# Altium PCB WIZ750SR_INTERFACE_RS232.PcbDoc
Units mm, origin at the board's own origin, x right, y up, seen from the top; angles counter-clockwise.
Board outline 83 x 65 mm, 2 copper layers (Top Layer, Bottom Layer), stack 0.325 mm thick; 76 components, 69 nets, 279 pads, 112 vias.
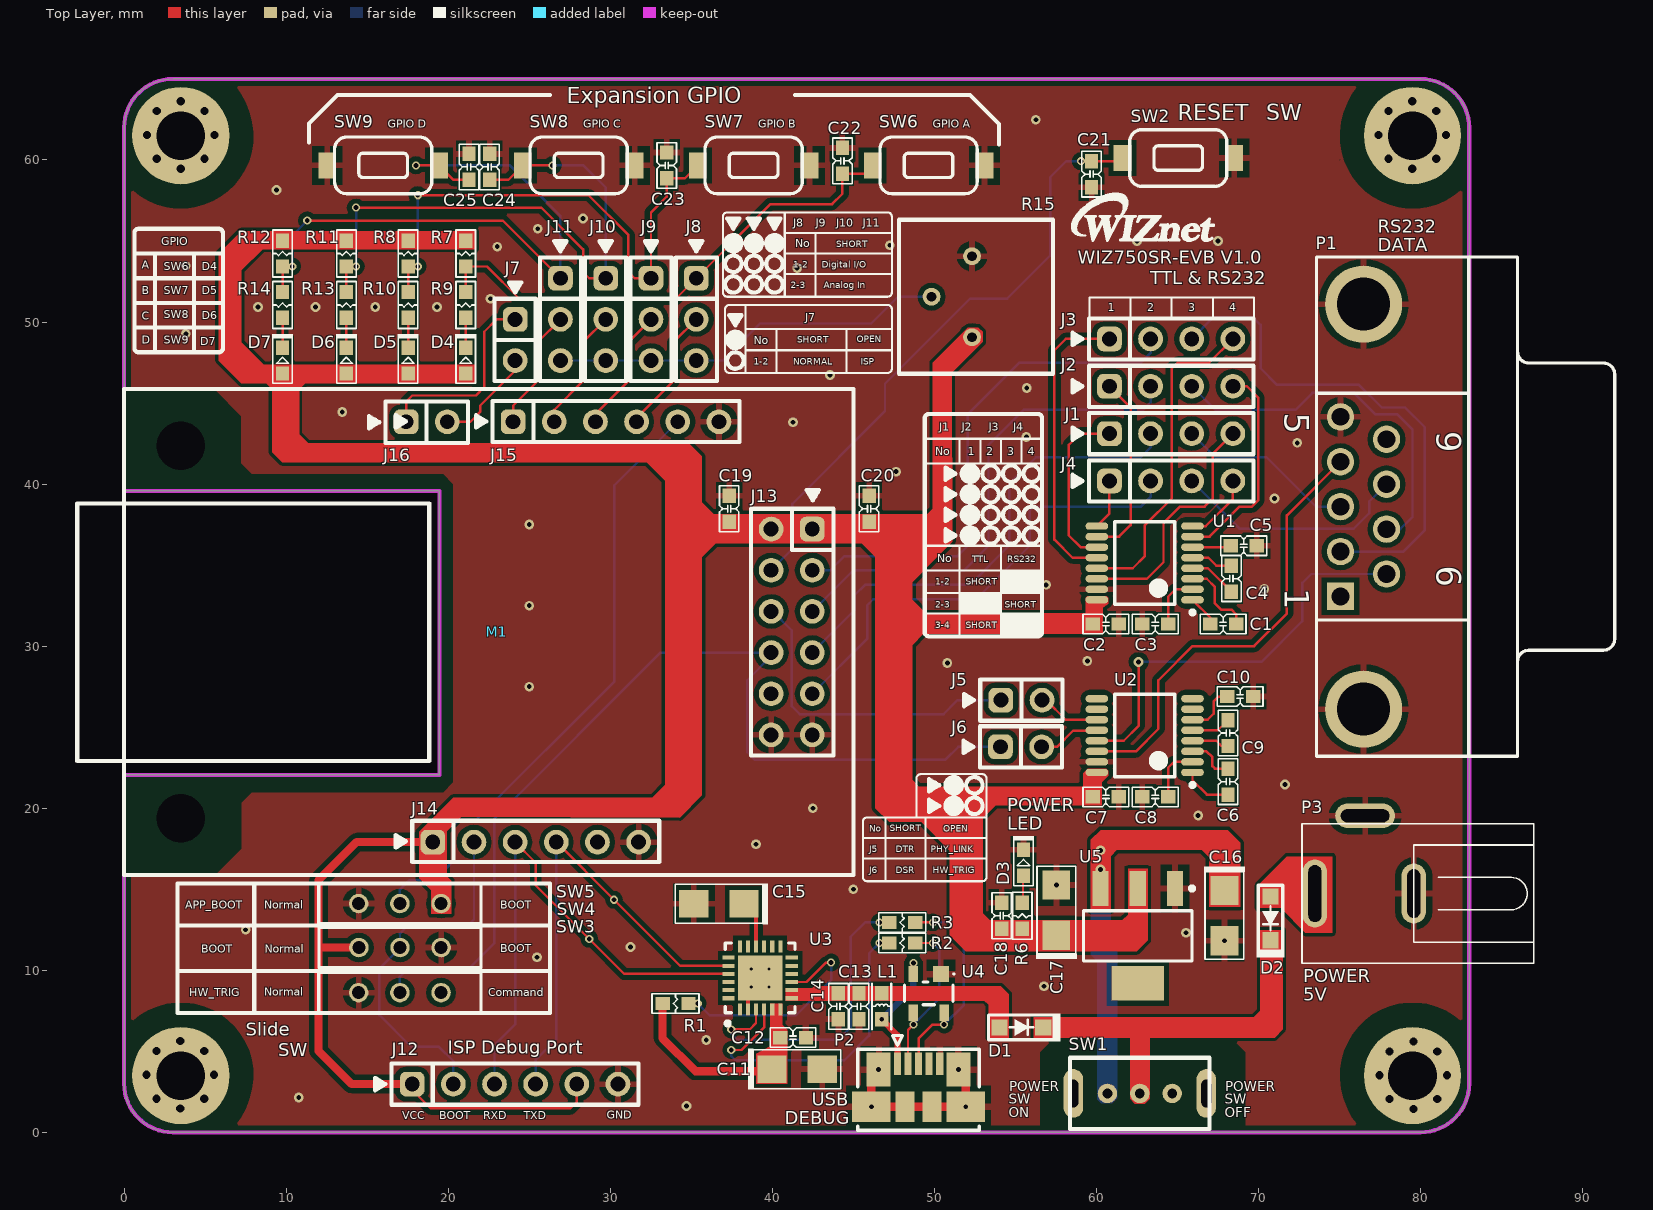
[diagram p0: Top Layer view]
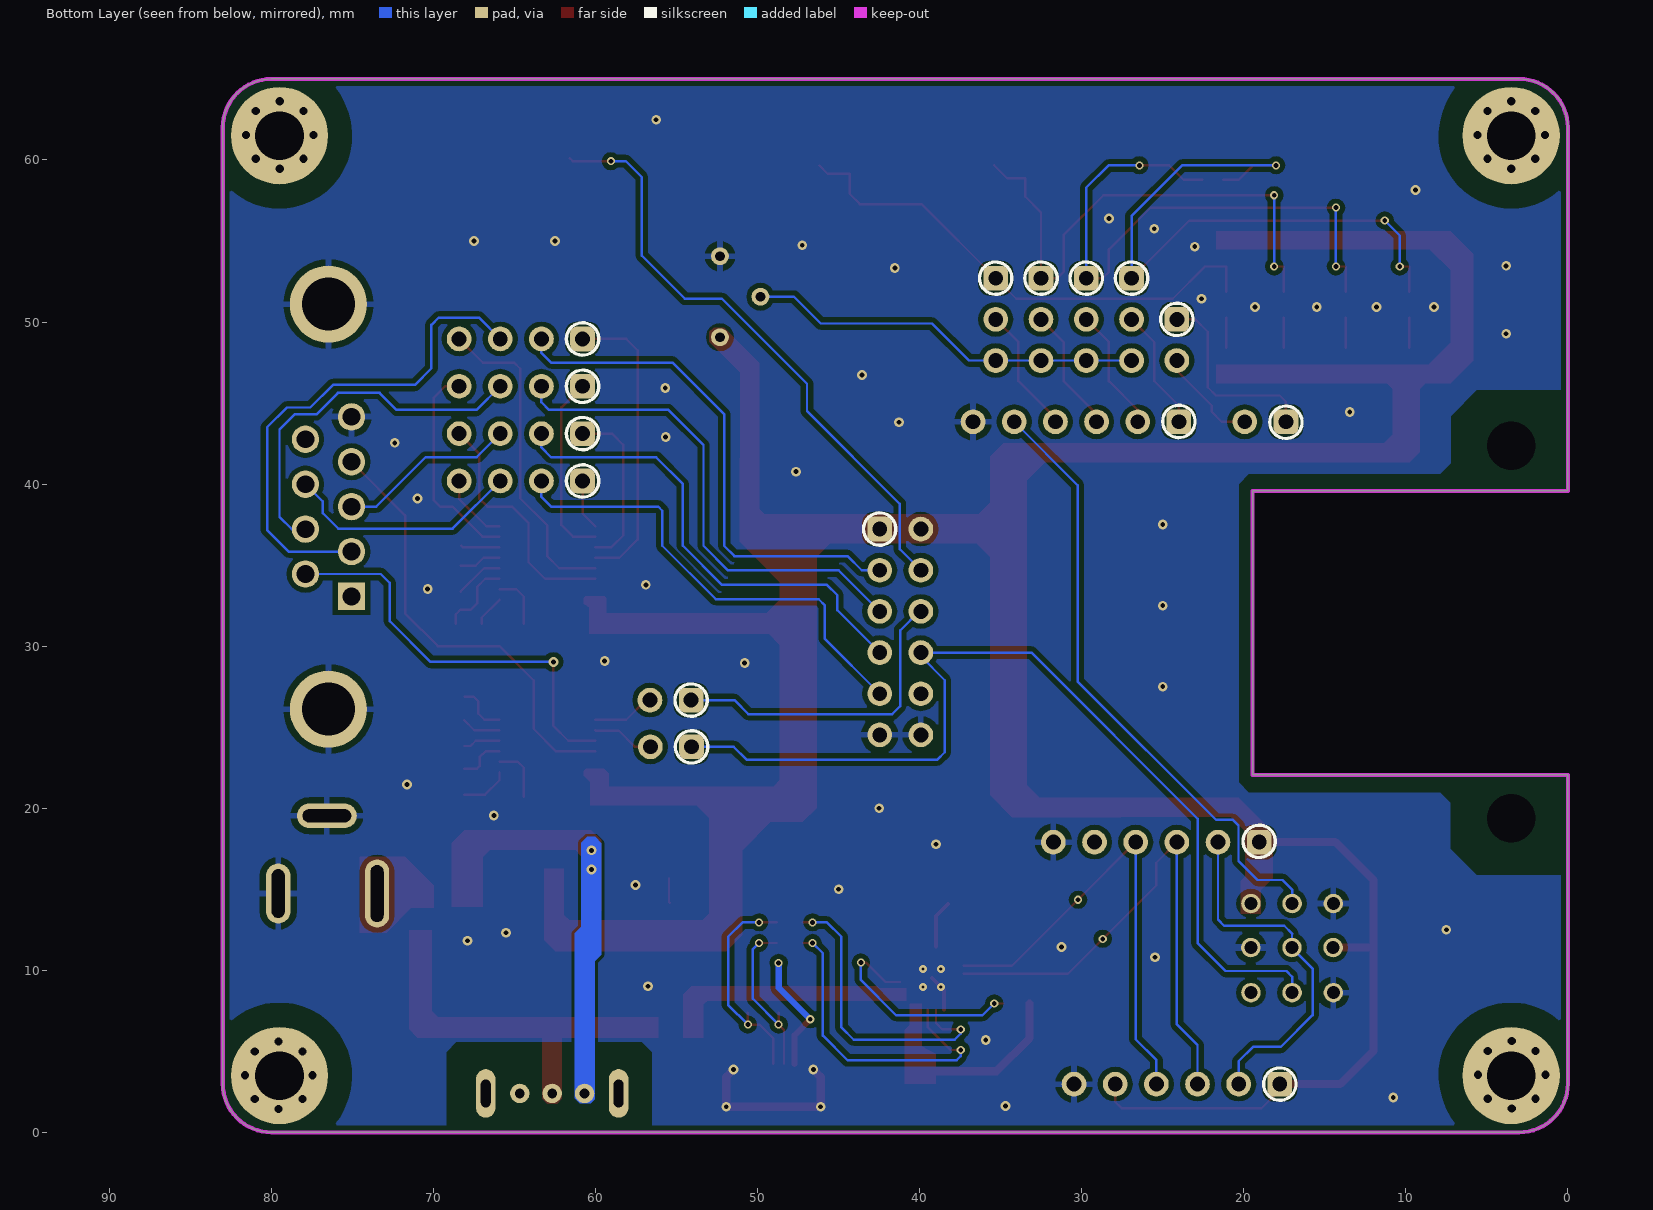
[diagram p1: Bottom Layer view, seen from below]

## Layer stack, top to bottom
Top Solder: solder mask 0.0102, Solder Resist, Dk 3.5
Top Layer: signal copper 0.0356
Dielectric 1: core 0.254, FR-4, Dk 4.2
Bottom Layer: signal copper 0.0356
Bottom Solder: solder mask 0.0102, Solder Resist, Dk 3.5

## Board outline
0,3 ccw(c3,3) 3,0 80,0 ccw(c80,3) 83,3 83,62 ccw(c80,62) 80,65 3,65 ccw(c3,62) 0,62 0,39.575 19.45,39.575 19.45,22.05 0,22.05

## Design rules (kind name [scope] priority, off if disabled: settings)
Clearance [All] p1: gap=0.15 except(0.205: Track-Region SMDPad-Region THPad-Region Via-Region Fill-Region Poly-Region Region-Region; 0.3: Track-Poly SMDPad-Poly THPad-Poly Via-Poly Fill-Poly Poly-Poly; 0.381: Arc-Poly)
HoleSize [All] p1: absolutevalues=TRUE maxlimit=4.064 minlimit=0.025 maxpercent=80.000 minpercent=20.000
MinimumSolderMaskSliver [All] p1: minsoldermaskwidth=0.1
PlaneClearance [All] p1: clearance=0.3
PlaneConnect [All] p1: planeconnectstyle=Direct reliefexpansion=0.508 reliefentries=4 reliefconductorwidth=0.254 reliefairgap=0.254
PolygonConnect PolygonConnect_2 [IsPad vs IsNamedPolygon('TOPGND') Or IsNamedPolygon('BOTGND')] p1: connectstyle=Relief reliefconductorwidth=0.381 reliefentries=4 polygonreliefangle="90 Angle" airgapwidth=0.381
PolygonConnect PolygonConnect_1 [IsVia] p2: connectstyle=Direct reliefconductorwidth=0.254 reliefentries=4 polygonreliefangle="90 Angle" airgapwidth=0.254
PolygonConnect [All] p3: connectstyle=Direct reliefconductorwidth=0.381 reliefentries=4 polygonreliefangle="90 Angle" airgapwidth=0.381
RoutingVias [All] p1: holewidth=0.3 width=0.5 viastyle="Through Hole" minholewidth=0.2 minwidth=0.5 maxholewidth=1 maxwidth=1.5
SilkToSilkClearance [All] p1: silktosilkclearance=0.1
SilkToSolderMaskClearance [IsPad] p1: minsilkscreentomaskgap=0 clearancetoexposedcopper=TRUE
SolderMaskExpansion [All] p1: expansion=0.1
Width [All] p1: maxlimit=0.508 minlimit=0.15 preferedwidth=0.15
24 further rules are at their usual default settings.

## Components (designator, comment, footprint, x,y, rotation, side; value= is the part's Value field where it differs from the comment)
C1 "0.1uF" CAP-0603 67.818,31.369 r180 top
C2 "0.1uF" CAP-0603 60.579,31.369 r0 top
C3 "0.1uF" CAP-0603 63.627,31.369 r180 top
C4 "0.1uF" CAP-0603 68.326,34.163 r270 top
C5 "0.1uF" CAP-0603 69.088,36.195 r0 top
C6 "0.1uF" CAP-0603 68.115,21.64 r270 top
C7 "0.1uF" CAP-0603 60.579,20.701 r0 top
C8 "0.1uF" CAP-0603 63.627,20.701 r180 top
C9 "0.1uF" CAP-0603 68.115,24.64 r270 top
C10 "0.1uF" CAP-0603 68.865,26.89 r0 top
C11 "4.7uF/16V" "CAP-A Size" 41.525,3.9 r0 top
C12 "0.1uF" CAP-0603 41.275,5.842 r180 top
C13 "1uF" CAP-0603 45.35,7.775 r90 top
C14 "0.1uF" CAP-0603 44.075,7.775 r90 top
C15 "4.7uF/16V" "CAP-A Size" 36.703,14.097 r180 top
C16 "10uF/16V" "CAP-A Size" 67.9,13.375 r270 top
C17 "10uF/16V" "CAP-A Size" 57.531,13.716 r90 top
C18 "0.1uF" CAP-0603 54.152,13.363 r270 top
C19 "0.1uF" CAP-0603 37.338,38.481 r270 top
C20 "0.1uF" CAP-0603 45.974,38.481 r270 top
C21 "0.1uF" CAP-0603 59.7,59.125 r90 top
C22 "0.1uF" CAP-0603 44.323,59.944 r270 top
C23 "0.1uF" CAP-0603 33.483,59.661 r270 top
C24 "0.1uF" CAP-0603 22.556,59.572 r270 top
C25 "0.1uF" CAP-0603 21.281,59.572 r270 top
D1 "BAT60A" D-BAT60A/SOD-323 55.372,6.477 r0 top (schematic designator D3)
D2 "BAT60A" D-BAT60A/SOD-323 70.739,13.208 r270 top (schematic designator D4)
D3 "GREEN-0603" LED-0603-RED 55.499,16.637 r90 top (schematic designator D5)
D4 "GREEN-0603" LED-0603-GREEN 21.082,47.625 r90 top (schematic designator D6)
D5 "GREEN-0603" LED-0603-GREEN 17.526,47.625 r90 top (schematic designator D7)
D6 "GREEN-0603" LED-0603-GREEN 13.716,47.625 r90 top (schematic designator D8)
D7 "GREEN-0603" LED-0603-GREEN 9.779,47.625 r90 top (schematic designator D9)
J1 "2.54mm 1x4 Pin Header DIP" IDC-1X4 60.799,43.115 r0 top
J2 "2.54mm 1x4 Pin Header DIP" IDC-1X4 60.799,46.036 r0 top
J3 "2.54mm 1x4 Pin Header DIP" IDC-1X4 60.799,48.957 r0 top
J4 "2.54mm 1x4 Pin Header DIP" IDC-1X4 60.799,40.194 r0 top
J5 "2.54mm 1x2 Pin Header DIP" IDC-1X2 54.102,26.67 r0 top
J6 "2.54mm 1x2 Pin Header DIP" IDC-1X2 54.075,23.787 r0 top
J7 "2.54mm 1x2 Pin Header DIP" IDC-1X2 24.13,50.165 r270 top
J8 "2.54mm 1x3 Pin Header DIP" IDC-1X3 35.306,52.705 r270 top
J9 "2.54mm 1x3 Pin Header DIP" IDC-1X3 32.512,52.705 r270 top
J10 "2.54mm 1x3 Pin Header DIP" IDC-1X3 29.718,52.705 r270 top
J11 "2.54mm 1x3 Pin Header DIP" IDC-1X3 26.924,52.705 r270 top
J12 "2.54mm 1x6 Pin Header DIP" IDC-1X6 17.775,2.975 r0 top
L1 "HH-1M1608-121JT" IND-0603 46.75,7.775 r90 top
M1 "WIZ750SR_TTL/232" WIZ750SR_V1.0_TTL/232 0,15.875 r0 top
P1 "D-SUB9-MALE" D-SUB9-MALE 85.979,38.608 r270 top
P2 "47346-0001" USB-MICRO-B(SMD) 49.022,0.127 r90 top
P3 "DC-JACK 2pi" "DC-JACK 2pi" 76.581,14.732 r90 top
R1 "4.7K" RES-0603 34.025,7.95 r180 top
R2 "22R" RES-0603 48.006,11.684 r180 top
R3 "22R" RES-0603 48.006,12.954 r180 top
R6 "330R" RES-0603 55.422,13.363 r90 top
R7 "4.7K" RES-0603 21.082,54.229 r90 top
R8 "4.7K" RES-0603 17.526,54.229 r90 top
R9 "330R" RES-0603 21.082,51.054 r90 top
R10 "330R" RES-0603 17.526,51.054 r90 top
R11 "4.7K" RES-0603 13.716,54.229 r90 top
R12 "4.7K" RES-0603 9.779,54.229 r90 top
R13 "330R" RES-0603 13.716,51.054 r90 top
R14 "330R" RES-0603 9.779,51.054 r90 top
R15 "WIW3386P" WIW3386P 52.324,51.562 r270 top
SW1 "SK-12D02" SK-12D02 62.675,2.4 r0 top
SW2 "IT-1101NHA-180G" IT-1101NHA 65.047,60.12 r0 top
SW3 "ITS-12H" ITS-12H 17.016,8.616 r180 top
SW4 "ITS-12H" ITS-12H 17.025,11.4 r0 top
SW5 "ITS-12H" ITS-12H 17.016,14.116 r180 top
SW6 "IT-1101NHA-180G" IT-1101NHA 49.641,59.666 r180 top
SW7 "IT-1101NHA-180G" IT-1101NHA 38.846,59.666 r180 top
SW8 "IT-1101NHA-180G" IT-1101NHA 28.051,59.666 r180 top
SW9 "IT-1101NHA-180G" IT-1101NHA 15.986,59.666 r0 top
U1 "SP3232EBEY" SP3232EBEY-TSSOP16 62.976,35.133 r180 top
U2 "SP3232EBEY" SP3232EBEY-TSSOP16 62.976,24.485 r180 top
U3 "CP2104-GM" CP2104_QFN24_PAD 39.243,9.525 r90 top
U4 "SP0503BAHTG" SP0503BAHTG 49.65,8.575 r270 top
U5 "IL1117C-33ET" IL1117C-33ET 62.55,12.125 r270 top

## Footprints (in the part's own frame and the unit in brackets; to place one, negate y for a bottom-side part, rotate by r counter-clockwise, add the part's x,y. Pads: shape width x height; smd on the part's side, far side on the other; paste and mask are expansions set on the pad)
CAP-0603 [mm] "Ceramic CAP 0603(1608)"
  rect 0.89x0.82 smd: 1(-0.8,0) 2(0.8,0)
  silkscreen extent -1.41,-0.6 1.41,0.6, body extent -0.93,-0.41 0.93,0.41, height 0.81
"CAP-A Size" [mm] "Tantal CAP A Size EIA/IECQ 3216"
  rect 1.8x1.7 smd: 1(-1.55,0) 2(1.55,0)
  silkscreen extent -3,-1.25 2.7,1.25, body extent -1.67,-0.78 1.72,0.82, height 1.75
CP2104_QFN24_PAD [mm] "QFN, 24-Leads, Body 4.00x4.00mm, Pitch 0.50mm, Thermal Pad 2.75x2.75mm, IPC Medium Density"
  rect 0.75x0.25 smd: 1(-1.95,1.25) 2(-1.95,0.75) 3(-1.95,0.25) 4(-1.95,-0.25) 5(-1.95,-0.75) 6(-1.95,-1.25) 13(1.95,-1.25) 14(1.95,-0.75) 15(1.95,-0.25) 16(1.95,0.25) 17(1.95,0.75) 18(1.95,1.25)
  rect 0.25x0.75 smd: 7(-1.25,-1.95) 8(-0.75,-1.95) 9(-0.25,-1.95) 10(0.25,-1.95) 11(0.75,-1.95) 12(1.25,-1.95) 19(1.25,1.95) 20(0.75,1.95) 21(0.25,1.95) 22(-0.25,1.95) 23(-0.75,1.95) 24(-1.25,1.95)
  rect 2.75x2.75 smd: 25(0,0)
  silkscreen extent -2.92,-2.15 2.15,2.15, body extent -2,-2 2,2, height 0.8
D-BAT60A/SOD-323 [mm]
  rect 1x1 smd: 1(1.35,0) 2(-1.35,0)
  silkscreen extent -2.03,-0.86 2.41,0.86, body extent -1.35,-0.68 1.35,0.67, height 0.79
D-SUB9-MALE [mm] "D-SUB9, MALE, Right Angle;"
  rect 1.69x1.69 hole 1.09: 1(5.54,-10.92)
  round 1.69 hole 1.09: 2(2.77,-10.92) 3(0,-10.92) 4(-2.77,-10.92) 5(-5.54,-10.92) 6(4.155,-8.08) 7(1.385,-8.08) 8(-1.385,-8.08) 9(-4.155,-8.08)
  round 4.76 hole 3.26: 10(-12.495,-9.5) 11(12.495,-9.5)
  silkscreen extent -15.4,-12.4 15.4,6, body extent -15.38,-12.55 15.43,6.05, height 12.57
"DC-JACK 2pi" [mm] "DC-JACK 2pi"
  oval 4.2x1.5 hole 0.8 slot 3.5 at 0 deg: 1(0,3.1)
  oval 1.5x3.7 hole 0.8 slot 3 at 90 deg: 2(4.8,0)
  oval 3.7x1.5 hole 0.8 slot 3 at 0 deg: 3(0,-3)
  silkscreen extent -4.3,-10.4 4.3,3.9, body extent -4.42,-10.49 5.05,3.99, height 11.18
IDC-1X2 [mil]
  rrect50% 60x60 hole 36: 1(0,0)
  round 60 hole 36: 2(100,0)
  silkscreen extent -90,-50 150,50, body extent -49,-49 151,51, height 336
IDC-1X3 [mil]
  rrect50% 60x60 hole 36: 1(0,0)
  round 60 hole 36: 2(100,0) 3(200,0)
  silkscreen extent -90,-50 250,50, body extent -46,-49 254,49, height 323
IDC-1X4 [mil]
  rrect50% 60x60 hole 36: 1(0,0)
  round 60 hole 36: 2(100,0) 3(200,0) 4(300,0)
  silkscreen extent -90,-50 350,50, body extent -49,-49 351,51, height 336
IDC-1X6 [mil] "6-Way 2.54 mm Male Header"
  rrect50% 60x60 hole 36: 1(0,0)
  round 60 hole 36: 2(100,0) 3(200,0) 4(300,0) 5(400,0) 6(500,0)
  silkscreen extent -90,-50 550,50, body extent -49,-49 551,51, height 336
IL1117C-33ET [mm] "SOT223, 4-Leads, Body 6.45x7.80mm (avg), Pitch 2.30mm, IPC Medium Density"
  rect 2.15x1 smd: 1(-2.925,2.3) 2(-2.925,0) 3(-2.925,-2.3)
  rect 2.15x3.25 smd: 4(2.925,0)
  silkscreen extent -3.05,-3.35 1.55,3.48, body extent -3.54,-3.25 3.54,3.25, height 1.65
IND-0603 [mm]
  rect 0.89x0.82 smd: 1(-0.8,0) 2(0.8,0)
  silkscreen extent -1.4,-0.6 1.4,0.6, body extent -0.8,-0.4 0.8,0.4, height 0.95
IT-1101NHA [mm]
  rect 1.1x1.6 smd: 1(-3.45,0) 2(3.45,0)
  silkscreen extent -3,-1.75 3,1.75, body extent -3.05,-1.85 3.05,1.85, height 2.5
ITS-12H [mm] "Silde Switch"
  round 1.2 hole 0.8: 1(0,0) 2(-2.54,0) 3(2.54,0)
  silkscreen extent -5,-1.25 5,1.25, body extent -5,-1.22 5,1.22, height 6.4
LED-0603-GREEN [mm] "LED-0603-GREEN"
  rect 0.89x0.82 smd: 1(-0.8,0) 2(0.8,0)
  silkscreen extent -1.41,-0.65 1.65,0.65, body extent -0.85,-0.45 0.85,0.45, height 0.9
LED-0603-RED [mm] "LED-0603-RED"
  rect 0.89x0.82 smd: 1(-0.8,0) 2(0.8,0)
  silkscreen extent -1.41,-0.65 1.65,0.65, body extent -0.85,-0.45 0.85,0.45, height 0.9
RES-0603 [mm] "RES-0603"
  rect 0.89x0.82 smd: 1(-0.8,0) 2(0.8,0)
  silkscreen extent -1.45,-0.6 1.45,0.6, body extent -0.82,-0.41 0.82,0.41, height 0.46
SK-12D02 [mm] "Angle Type, DIP Switch, ON-ON, DC 50V, 0.3A"
  round 1.2 hole 0.6: 1(-2,0) 2(0,0) 3(2,0)
  oval 1.2x3 hole 0.6 slot 1.7 at 90 deg: 4(-4.1,0) 5(4.1,0)
  silkscreen extent -4.3,-2.2 4.3,2.2, body extent -4.31,-6.22 4.31,2.15, height 5
SP0503BAHTG [mm] "SOT143, 4-Leads, Body 2.92x2.37mm, Pitch 1.90mm, IPC Medium Density"
  rect 1x1 smd: 1(-1.2,0.75)
  rect 1x0.6 smd: 2(-1.2,-0.95) 3(1.2,-0.95) 4(1.2,0.95)
  silkscreen extent -1.25,-1.5 0.7,1.6, body extent -0.7,-1.52 0.7,1.52, height 1.22
SP3232EBEY-TSSOP16 [mm] "True +3.0V to +5.5V RS-232 Transceivers"
  oval 1.4x0.45 smd: 1(-2.95,2.275) 2(-2.95,1.625) 3(-2.95,0.975) 4(-2.95,0.325) 5(-2.95,-0.325) 6(-2.95,-0.975) 7(-2.95,-1.625) 8(-2.95,-2.275) 9(2.95,-2.275) 10(2.95,-1.625) 11(2.95,-0.975) 12(2.95,-0.325) 13(2.95,0.325) 14(2.95,0.975) 15(2.95,1.625) 16(2.95,2.275)
  silkscreen extent -3.08,-2.55 1.85,3.17, body extent -3.16,-2.49 3.12,2.51, height 1.09
USB-MICRO-B(SMD) [mm] "MOLEX SD-47346-001"
  rect 1.38x0.45 smd: 1(4.11,1.3) 2(4.11,0.65) 3(4.11,0) 4(4.11,-0.65) 5(4.11,-1.3)
  rect 2.1x1.475 smd: 6(3.75,2.462) 7(3.75,-2.462)
  rect 1.9x2.375 smd: 8(1.45,2.913) 11(1.45,-2.913)
  rect 1.9x1.175 smd: 9(1.45,0.837) 10(1.45,-0.837)
  silkscreen extent 0,-3.75 5.85,3.75, body extent -0.43,-4.1 5,4.1, height 2.98
WIW3386P [mm] "Potentiometer 10KR, Hongxing, 8mm shaft"
  round 1.1 hole 0.6: 1(2.5,0) 2(0,-2.5) 3(-2.5,0)
  silkscreen extent -4.75,-4.5 4.75,5, body extent -3.3,-3.3 3.3,3.75, height 4.7
WIZ750SR_V1.0_TTL/232 [mil] "WIZ750SR_V1.0, Serial to Ethernet Module, W7500P"
  round 0 hole 118.11: CH_GND(137.8,137.8) CH_GND(137.8,1043.31)
  rrect50% 60x60 hole 36: D1(1671.89,840.55) E1(945,1101.1) I1(750,80) W1(685,1101.1)
  round 60 hole 36: D2(1571.89,840.55) D3(1671.89,740.55) D4(1571.89,740.55) D5(1671.89,640.55) D6(1571.89,640.55) D7(1671.89,540.55) D8(1571.89,540.55) D9(1671.89,440.55) D10(1571.89,440.55) D11(1671.89,340.55) D12(1571.89,340.55) E2(1045,1101.1) E3(1145,1101.1) E4(1245,1101.1) E5(1345,1101.1) E6(1445,1101.1) I2(850,80) I3(950,80) I4(1050,80) I5(1150,80) I6(1250,80) W2(785,1101.1)
  silkscreen extent -114,0 1772,1181, body extent 625,29 1715,1149, height 325

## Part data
C1 C2 C3 C4 C5 C6 C7 C8 C9 C10 C12 C13 C14 C18 C19 C20 C21 C22 C23 C24 C25: library part CAP-0603, "Ceramic CAP 0603(1608)"
C11 C15 C16 C17: library part "CAP-A Size", "Tantla CAP A Size EIA/IECQ 3216"
D1 D2: library part DIODE-BAT60A, "Silicon Schottky Diode"
D3 D4 D5 D6 D7: library part LED-0603, "LED-0603"
J5 J6 J7: library part "Header 2", "Header, 2-Pin"
J12: library part "Header 6", "Header, 6-Pin"
L1: library part IND-0603, "Inductor 0603(1608)"
M1: library part WIZ750SR_V1.0_TTL/232, "Serial to ethernet module, 45mmx30mm, TTL/232"
P1: "D-SUB-9, MALE,  Right Angle"
P2: "MICRO USB B Type"
R1 R2 R3 R6 R7 R8 R9 R10 R11 R12 R13 R14: library part RES-0603, "RES-0603"
R15: "Potentiometer"
SW1: "3 Port SW , SPDT ON-ON , 50V, 0.3A"
SW2 SW6 SW7 SW8 SW9: "TACT Switch (SMD)"
SW3 SW4 SW5: "Slide Switch"
U1 U2: "True +3.0V to +5.5V RS-232 Transceivers"
U3: "USB to UART Bridge, SiliconLabs"
U4: "Little Fuse, Silicon Protection Array Products"
U5: "1A, 3.3V"

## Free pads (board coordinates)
  round 6 hole 3: ""(3.5,3.5) ""(3.5,61.5) ""(79.5,3.5) ""(79.5,61.5)

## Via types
v1: diameter 0.6, hole 0.3, Top Layer to Bottom Layer, tented both sides, 53 vias
v2: diameter 0.762, hole 0.508, Top Layer to Bottom Layer, tented both sides, 32 vias
v3: diameter 0.5, hole 0.3, Top Layer to Bottom Layer, tented both sides, 19 vias
v4: diameter 0.5, hole 0.2, Top Layer to Bottom Layer, 4 vias
v5: diameter 0.5, hole 0.3, Top Layer to Bottom Layer, 4 vias

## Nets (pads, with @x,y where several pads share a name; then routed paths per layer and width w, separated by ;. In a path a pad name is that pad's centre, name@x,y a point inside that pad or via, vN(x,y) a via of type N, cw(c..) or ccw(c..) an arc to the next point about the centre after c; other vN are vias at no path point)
5V: C16.1 SW1.1 U5.3
  other v1: 60.25,16.225 60.25,17.4
ADC0: J8.3 J9.3 J10.3 J11.3 R15.2 | length 24.5
  Bottom Layer w0.15: J11.3 J10.3 J9.3 J8.3 36.957,47.625 39.243,49.911 46.101,49.911 47.752,51.562 R15.2
APP_BOOT: M1.E5 SW5.1 | length 38.3
  Bottom Layer w0.15: SW5.1 17.016,14.984 17.602,15.57 19.145,15.57 20.325,16.75 20.325,18.925 20.675,19.275 21.7,19.275 30.25,27.825 30.25,39.93 M1.E5
BOOT: J12.2 M1.I2 SW4.1 | length 22.4
  Bottom Layer w0.15: 17.016,12.266 17.501,12.751 21.209,12.751 21.59,13.132 M1.I2 ; 17.025,12.257 SW4.1 17.025,11.375 15.75,10.1 15.75,7.237 17.715,5.272 19.428,5.272 20.315,4.385 J12.2
CON_CTS: J4.2 M1.D9 | length 29.4
  Bottom Layer w0.15: M1.D9 45.847,30.446 45.847,32.512 46.228,32.893 52.578,32.893 55.88,36.195 55.88,38.354 56.134,38.608 62.738,38.608 63.339,39.209 J4.2
CON_RTS: J2.2 M1.D5 | length 30.8
  Bottom Layer w0.15: M1.D5 44.992,34.671 51.816,34.671 53.34,36.195 53.34,42.418 55.499,44.577 62.865,44.577 63.339,45.051 J2.2
CON_RXD: J3.2 M1.D3 | length 32
  Bottom Layer w0.15: M1.D3 43.575,34.685 44.45,35.56 51.435,35.56 52.07,36.195 52.07,44.323 55.245,47.498 62.738,47.498 63.339,48.099 J3.2
CON_TXD: J1.2 M1.D7 | length 29.7
  Bottom Layer w0.15: M1.D7 45.085,32.224 45.085,33.147 45.72,33.782 52.197,33.782 54.61,36.195 54.61,40.005 56.261,41.656 62.738,41.656 63.339,42.257 J1.2
D+: P2.3 R3.1 U4.4 | length 13.5
  Top Layer w0.15: R3.1 v3(49.911,12.954) ; P2.3 49.022,5.797 49.875,6.65 v3(50.6,6.65) U4.4
  Bottom Layer w0.15: v3(49.911,12.954) 50.927,12.954 51.816,12.065 51.816,7.866 v3(50.6,6.65)
D-: P2.2 R2.1 U4.3 | length 10.2
  Top Layer w0.15: P2.2 48.372,6.322 v3(48.7,6.65) U4.3 ; R2.1 v3(49.911,11.684)
  Bottom Layer w0.15: v3(48.7,6.65) 50.292,8.242 50.292,11.303 v3(49.911,11.684)
DB_CTS: J4.3 P1.8 | length 14.8
  Bottom Layer w0.15: J4.3 68.823,37.25 75.875,37.25 76.835,38.21 76.835,38.929 P1.8
DB_DSR: P1.6 U2.13 | length 25.8
  Top Layer w0.15: U2.13 61.685,24.16 62.6,25.075 v1(62.6,29.025)
  Bottom Layer w0.15: v1(62.6,29.025) 70.175,29.025 72.7,31.55 72.7,33.9 73.253,34.453 P1.6
DB_DTR: P1.4 U2.14 | length 27.7
  Top Layer w0.15: U2.14 62.435,23.51 63.825,24.9 63.825,27.9 65.925,30 69.725,30 71.75,32.025 71.75,38.069 P1.4
DB_RTS: J2.3 P1.7 | length 22.9
  Bottom Layer w0.15: J2.3 67.34,44.575 72.275,44.575 73.325,45.625 75.9,45.625 77.225,44.3 78.575,44.3 79.502,43.373 79.502,37.977 78.748,37.223 P1.7
DB_RXD: J3.3 P1.2 | length 31.4
  Bottom Layer w0.15: J3.3 67.197,50.275 69.675,50.275 70.125,49.825 70.125,47.15 71.15,46.125 76.2,46.125 77.6,44.725 79.05,44.725 80.264,43.511 80.264,37.164 78.938,35.838 P1.2
DB_TXD: J1.3 P1.3 | length 11
  Bottom Layer w0.15: J1.3 67.338,41.656 70.485,41.656 73.533,38.608 P1.3
DSR: J6.1 M1.D8 SW3.1 | length 59.6
  Bottom Layer w0.15: SW3.1 17.016,9.599 17.374,9.957 21.132,9.957 22.85,11.675 22.85,19.35 33.105,29.605 M1.D8 39.926,29.376 38.45,27.9 38.45,23.45 38.9,23 50.686,23 51.473,23.787 J6.1 J6.1@54.05,23.762
DTR: J5.1 M1.D6 | length 20.1
  Bottom Layer w0.15: M1.D6 40.03,32.145 41.2,30.975 41.2,26.3 41.7,25.8 50.565,25.8 51.435,26.67 J5.1 J5.1@53.994,26.562
EXPANSION_GPIO_A: J8.2 M1.E4 | length 7.8
  Top Layer w0.15: M1.E4 31.623,44.069 33.909,46.355 33.909,48.768 J8.2
EXPANSION_GPIO_B: J9.2 M1.E3 | length 7.7
  Top Layer w0.15: M1.E3 29.083,44.323 31.115,46.355 31.115,48.768 J9.2
EXPANSION_GPIO_C: J10.2 M1.E2 | length 7.6
  Top Layer w0.15: M1.E2 26.543,44.577 28.321,46.355 28.321,48.768 J10.2
EXPANSION_GPIO_D: J11.2 M1.E1 | length 7.5
  Top Layer w0.15: M1.E1 24.003,44.831 25.527,46.355 25.527,48.768 J11.2
GND: C2.2 C3.2 C5.2 C7.2 C8.2 C10.2 C11.2 C12.1 C13.1 C14.1 C15.2 C16.2 C17.2 C18.1 C19.1 C20.1 C21.1 C22.1 C23.1 C24.1 C25.1 D3.2 J12.6 M1.D11 M1.D12 M1.E6 M1.I6 P1.5 P1.10 P1.11 P2.5 P2.6 P2.7 P2.8 P2.9 P2.10 P2.11 P3.2 P3.3 R15.3 SW2.2 SW3.3 SW4.3 SW5.3 SW6.1 SW7.1 SW8.1 SW9.1 U1.15 U2.15 U3.2 U3.25 U4.1 U5.1 | length 13.1
  Top Layer w0.25: U3.2 38.493,8.775 v4(38.693,8.975) U3.25
  Top Layer w0.508: v1(46.56,3.877) 46.109,3.427 v1(46.109,1.577) P2.9 P2.10 v1(51.935,1.577) 51.935,3.427 v1(51.484,3.877)
  other v1: 34.7,1.625 10.775,2.15 35.925,5.7 56.769,9.017 25.475,10.8 31.242,11.43 67.9,11.825 65.532,12.319 7.5,12.5 45,15 57.531,15.266 38.989,17.78 66.275,19.55 42.5,20 71.628,21.463 25,27.5 50.8,28.956 59.436,29.083 25,32.5 70.358,33.528 56.896,33.782 25,37.5 70.993,39.116 47.625,40.767 72.39,42.545 55.675,42.9 41.275,43.815 13.462,44.45 55.7,45.925 43.561,46.736 3.81,49.276 8.255,50.927 11.811,50.927 15.494,50.927 19.304,50.927 22.606,51.435 41.529,53.34 3.81,53.467 23.025,54.65 47.244,54.737 62.5,55 67.5,55 25.527,55.753 28.321,56.388 9.4,58.15 56.261,62.484
  other v4: 39.793,8.975 38.693,10.075 39.793,10.075
LED_SW0: C22.2 J8.1 R7.1 R9.2 SW6.2 | length 31.6
  Top Layer w0.15: R9.2 R7.1 22.39,53.429 24.384,51.435 34.036,51.435 J8.1 39.878,57.277 43.688,57.277 44.323,57.912 C22.2 45.669,59.144 SW6.2@46.186,59.661
LED_SW1: C23.2 J9.1 R8.1 R10.2 SW7.2 | length 33.2
  Top Layer w0.15: R10.2 R8.1 v3(18.123,53.429) ; v3(18.123,57.823) 28.664,57.823 31.115,55.372 31.115,53.086 31.496,52.705 J9.1 32.512,56.769 33.483,57.74 C23.2 34.591,58.861 SW7.2
  Bottom Layer w0.15: v3(18.123,53.429) v3(18.123,57.823)
LED_SW2: C24.2 J10.1 R11.1 R13.2 SW8.2 | length 37.5
  Top Layer w0.15: R13.2 R11.1 v3(14.313,53.429) ; v3(14.313,57.061) 25.743,57.061 28.321,54.483 28.321,53.086 28.702,52.705 J10.1 ; C24.2 23.707,58.772 SW8.2 v3(26.44,59.666)
  Bottom Layer w0.15: v3(14.313,53.429) v3(14.313,57.061) ; v3(26.44,59.666) 28.345,59.666 29.718,58.293 J10.1
LED_SW3: C25.2 J11.1 R12.1 R14.2 SW9.2 | length 40.2
  Top Layer w0.15: R14.2 R12.1 v3(10.376,53.429) ; v3(11.303,56.261) 23.368,56.261 J11.1 ; v3(18.01,59.666) SW9.2 20.33,58.772 C25.2
  Bottom Layer w0.15: v3(10.376,53.429) 10.376,55.334 v3(11.303,56.261) ; v3(18.01,59.666) 23.811,59.666 26.924,56.553 J11.1
NetC1_1: C1.1 U1.3 | length 4.8
  Top Layer w0.15: U1.3 66.807,34.158 67.31,33.655 67.31,32.639 67.691,32.258 68.326,32.258 68.618,31.966 C1.1
NetC1_2: C1.2 U1.1 | length 1.9
  Top Layer w0.15: U1.1 67.018,31.766 C1.2
NetC3_1: C3.1 U1.2 | length 3.4
  Top Layer w0.15: C3.1 64.427,33.058 64.877,33.508 U1.2
NetC4_1: C4.1 U1.5 | length 2.6
  Top Layer w0.15: U1.5 66.904,35.458 67.399,34.963 C4.1
NetC4_2: C4.2 U1.4 | length 3
  Top Layer w0.15: U1.4 66.881,34.808 C4.2
NetC5_1: C5.1 U1.6 | length 2.4
  Top Layer w0.15: U1.6 68.201,36.108 C5.1
NetC6_1: C6.1 U2.3 | length 3
  Top Layer w0.15: U2.3 66.79,23.51 67.15,23.15 67.15,22.6 67.31,22.44 C6.1
NetC6_2: C6.2 U2.1 | length 3
  Top Layer w0.15: U2.1 65.926,21.724 66.81,20.84 C6.2
NetC8_1: C8.1 U2.2 | length 3.4
  Top Layer w0.15: C8.1 64.427,22.502 64.785,22.86 U2.2
NetC9_1: C9.1 U2.5 | length 2.4
  Top Layer w0.15: U2.5 67.485,24.81 C9.1
NetC9_2: C9.2 U2.4 | length 2.3
  Top Layer w0.15: U2.4 67.39,24.16 67.71,23.84 C9.2
NetC10_1: C10.1 U2.6 | length 3.2
  Top Layer w0.15: U2.6 66.86,25.46 67.225,25.825 67.225,26.575 67.54,26.89 C10.1
NetC15_1: C15.1 U3.16 | length 2.9
  Top Layer w0.25: C15.1 38.993,13.357 U3.16
NetD1_1: D1.1 D2.1 SW1.2
NetD2_2: D2.2 P3.1
NetD3_1: D3.1 R6.2 | length 1.5
  Top Layer w0.15: R6.2 55.468,14.209 D3.1@55.468,15.677
NetD4_2: D4.2 R9.1 | length 1.8
  Top Layer w0.15: D4.2 R9.1
NetD5_2: D5.2 R10.1 | length 1.8
  Top Layer w0.15: D5.2 R10.1
NetD6_2: D6.2 R13.1 | length 1.8
  Top Layer w0.15: D6.2 R13.1
NetD7_2: D7.2 R14.1 | length 1.8
  Top Layer w0.15: D7.2 R14.1
NetJ1_1: J1.1 U1.11 | length 10.4
  Top Layer w0.15: U1.11 59.015,36.108 58.293,36.83 58.293,42.418 58.99,43.115 J1.1
NetJ1_4: J1.4 U1.14 | length 15.1
  Top Layer w0.15: U1.14 63.114,34.158 64.135,35.179 64.135,37.592 65.151,38.608 66.675,38.608 67.183,39.116 67.183,41.879 J1.4
NetJ2_1: J2.1 U1.10 | length 11.5
  Top Layer w0.15: U1.10 61.396,36.758 62.103,37.465 62.103,44.732 J2.1
NetJ2_4: J2.4 U1.7 | length 13.2
  Top Layer w0.15: U1.7 66.984,36.758 68.834,38.608 69.596,38.608 69.977,38.989 69.977,45.339 69.28,46.036 J2.4
NetJ3_1: J3.1 U1.12 | length 18.5
  Top Layer w0.15: U1.12 58.522,35.458 57.404,36.576 57.404,48.26 58.101,48.957 J3.1
NetJ3_4: J3.4 U1.13 | length 20.1
  Top Layer w0.15: U1.13 62.24,34.808 62.992,35.56 62.992,37.465 64.643,39.116 64.643,47.117 65.024,47.498 66.96,47.498 J3.4
NetJ4_1: J4.1 U1.9 | length 3.1
  Top Layer w0.15: U1.9 60.799,38.181 J4.1
NetJ4_4: J4.4 U1.8 | length 4.3
  Top Layer w0.15: U1.8 66.745,37.408 68.419,39.082 J4.4
NetJ5_2: J5.2 U2.11 | length 3.9
  Top Layer w0.15: J5.2 56.896,26.67 58.106,25.46 U2.11
NetJ6_2: J6.2 U2.12 | length 3.8
  Top Layer w0.15: J6.2 57.569,23.787 58.567,24.785 60.001,24.785 U2.12
NetL1_1: L1.1 P2.1 U4.2 | length 8.1
  Top Layer w0.35: U4.2 v3(48.7,10.45)
  Top Layer w0.381: v5(46.75,6.975) 47.722,6.003 P2.1
  Bottom Layer w0.381: v5(46.75,6.975) 48.7,8.925 v3(48.7,10.45)
NetR1_1: R1.1 U3.9 | length 14
  Top Layer w0.15: R1.1 v5(35.4,7.95) ; U3.9 42.1,9.275 43.3,10.475 v5(43.625,10.475)
  Bottom Layer w0.15: v5(35.4,7.95) 36.125,7.225 41.45,7.225 43.625,9.4 v5(43.625,10.475)
NRESET: C21.2 M1.D4 SW2.1 | length 37.7
  Top Layer w0.15: v5(59.05,59.925) C21.2 61.402,59.925 SW2.1
  Bottom Layer w0.15: M1.D4 41.225,35.984 41.225,38.775 46.95,44.5 46.95,46.188 52.197,51.435 54.483,51.435 57.15,54.102 57.15,58.95 58.125,59.925 v5(59.05,59.925)
U_RXD: J12.3 M1.I3 U3.21 | length 32.8
  Top Layer w0.15: M1.I3 25.4,16.637 25.4,15.24 v3(28.702,11.938) 30.865,9.775 U3.21
  Bottom Layer w0.15: J12.3 22.855,5.38 24.13,6.655 M1.I3
U_TXD: J12.4 M1.I4 U3.20 | length 29.2
  Top Layer w0.15: M1.I4 v3(30.226,14.351) 34.302,10.275 U3.20
  Bottom Layer w0.15: J12.4 25.395,4.47 26.67,5.745 M1.I4
USB_3.3V: C11.1 C12.2 R1.2 U3.5 U3.6 | length 9.9
  Top Layer w0.508: R1.2 33.225,5.8 35.254,3.771 39.975,3.771 C11.1
USB_5V: C13.2 C14.2 D1.2 L1.2 U3.7 U3.8
USB_D+: R3.2 U3.3 | length 19
  Top Layer w0.15: v3(37.465,6.35) 38.608,6.35 38.993,6.735 U3.3 ; v3(46.609,12.954) R3.2
  Bottom Layer w0.15: v3(37.465,6.35) 37.465,6.096 37.846,5.715 44.069,5.715 44.831,6.477 44.831,12.065 45.72,12.954 v3(46.609,12.954)
USB_D-: R2.2 U3.4 | length 19.9
  Top Layer w0.15: v3(37.465,5.08) 38.1,5.08 39.493,6.473 U3.4 ; v3(46.609,11.684) R2.2
  Bottom Layer w0.15: v3(37.465,5.08) 37.465,4.699 37.719,4.445 44.45,4.445 45.974,5.969 45.974,11.049 v3(46.609,11.684)
VDD_3.3V: C2.1 C7.1 C17.1 C18.2 C19.2 C20.2 D4.1 D5.1 D6.1 D7.1 J12.1 J12.5 M1.D1 M1.D2 M1.I1 R6.1 R7.2 R8.2 R11.2 R12.2 R15.1 SW4.2 SW5.2 U1.16 U2.16 U5.2 | length 39.9
  Top Layer w0.15: J12.1 17.775,2.625 18.925,1.475 27.525,1.475 27.935,1.885 J12.5
  Top Layer w0.508: 12.05,11.4 SW4.2 ; J12.1 14.043,2.975 12,5.018 12,15.556 14.351,17.907 M1.I1
W7500P_NRST: J7.2 M1.W2 | length 6.4
  Top Layer w0.15: M1.W2 21.364,43.843 21.971,44.45 21.971,44.831 24.13,46.99 J7.2
WDT_NRST: J7.1 M1.W1 | length 12.1
  Top Layer w0.15: M1.W1 17.399,45.085 17.78,45.466 21.717,45.466 22.225,45.974 22.225,49.403 22.987,50.165 J7.1
pads on no net: M1.CH_GND M1.D10 M1.I5 P1.1 P1.9 P2.4 SW1.3 SW1.4 SW1.5 SW3.2 U2.7 U2.8 U2.9 U2.10 U3.1 U3.10 U3.11 U3.12 U3.13 U3.14 U3.15 U3.17 U3.18 U3.19 U3.22 U3.23 U3.24 U5.4
copper on no net:
  other v2: 79.555,1.438 3.468,1.463 78.082,2.048 81.028,2.048 1.995,2.074 4.941,2.074 77.472,3.521 81.638,3.521 1.385,3.546 5.551,3.546 78.082,4.994 81.028,4.994 1.995,5.019 4.941,5.019 79.555,5.604 3.468,5.629 3.493,59.463 79.488,59.464 2.02,60.073 4.966,60.073 78.015,60.074 80.961,60.074 1.41,61.546 5.576,61.546 77.405,61.547 81.571,61.547 2.02,63.019 4.966,63.019 78.015,63.02 80.961,63.02 3.493,63.629 79.488,63.63

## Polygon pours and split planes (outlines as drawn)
GND on Bottom Layer "BOTGND" (solid, remove dead copper, pour order 6): -1.27,67.31 86.36,67.31 86.36,-2.54 -1.27,-2.54
GND on Top Layer "TOPGND" (solid, remove dead copper, pour order 8): -1.27,67.31 86.36,67.31 86.36,-2.54 -1.27,-2.54

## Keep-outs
Keep-Out Layer:
  the board outline again, w0.254

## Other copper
Top Layer:
  pour cut-out: 5.611,45.811 -0.012,45.811 -0.012,39.636 7.239,39.637 19.525,39.636 19.45,22.05 7.25,22.05 7.25,21.5 7.25,20.955 7.239,20.32 7.874,20.955 19.685,20.955 20.32,21.59 20.32,40.005 19.685,40.64 7.885,40.64 7.239,41.286 7.239,44.183
  pour cut-out: 56.515,0 69.215,0 69.215,4.953 68.58,5.588 57.15,5.588 56.515,4.953
  pour cut-out: 7.251,22.05 0,22.05 0,15.875 5.635,15.875 7.251,17.491
  region net NetD2_2: 74.549,12.726 74.549,17.018 72.771,17.018 71.755,17.018 69.977,15.24 69.977,13.843 71.374,13.843 72.898,12.319 74.549,12.319
  region net NetD1_1: 56.134,7.112 56.134,5.842 61.95,5.842 62,5.842 62.075,5.842 62.075,2.06 62.357,1.778 62.992,1.778 63.275,2.061 63.275,5.842 63.35,5.842 70.992,5.842 71.501,6.351 71.501,7.112 71.501,12.475 70.1,12.475 70.1,7.775 70.1,7.5 69.712,7.112
  region net VDD_3.3V: 51.946,11.171 50.961,12.159 50.961,17.365 49.176,19.15 47.2,19.15 46.349,20.001 46.349,21.175 46.349,34.96 46.349,35.526 45.525,36.35 36.5,36.35 35.65,35.5 35.65,20.789 34.28,19.424 20.798,19.468 19.908,18.585 19.902,17.301 19.895,15.805 20.175,15.524 20.175,13.475 18.95,13.475 18.95,14.925 18.2,15.675 18.2,17.275 18.2,18.55 20.3,20.65 32.6,20.65 33.4,21.45 33.4,40.2 32.25,41.35 9.75,41.35 9.144,41.956 9.144,45.847 8.766,46.225 7.242,46.225 5.842,47.625 5.842,54.229 7.213,55.6 21.7,55.6 21.7,54.5 8.55,54.5 7.239,53.189 7.239,48.761 8.625,47.375 9.275,47.375 21.7,47.375 21.7,46.225 11.173,46.225 10.795,45.847 10.795,43.08 11.35,42.525 34.85,42.525 35.65,41.725 35.65,38.875 36.375,38.15 46.049,38.15 49.569,38.15 49.911,38.492 49.911,47.498 52.07,49.657 52.705,49.657 52.975,49.387 52.975,48.784 51.06,46.862 51.1,36.428 50.187,35.509 48.625,33.938 48.625,32.866 49.47,32.021 59.325,32.021 59.325,32.976 59.424,33.075 60.624,33.075 60.723,32.978 60.729,32.603 60.384,32.359 60.384,32.021 60.159,30.869 60.384,32.021 60.384,30.758 49.319,30.758 48.625,30.064 48.625,21.75 49.039,21.336 59.173,21.336 59.173,22.148 59.45,22.425 60.6,22.425 60.714,22.312 60.717,22.006 60.316,21.601 60.316,20.193 53.789,20.193 52.974,19.378 52.974,13.526 53.419,13.081 61.595,13.081 61.95,13.436 61.95,16.256 63.15,16.256 63.15,11.842 62.487,11.179
  region net USB_3.3V: 39.875,7.925 40.625,7.925 40.625,6.625 40.925,6.325 40.925,3 39,3 39,4.45 39,4.85 39.875,5.325
  region net 5V: 59.65,13.675 60.875,13.675 60.875,17.05 61.25,17.425 66.5,17.425 66.95,16.975 66.95,13.925 68.875,13.925 68.875,17.25 68.875,17.875 68.1,18.65 60.25,18.65 59.65,18.05
  region net USB_5V: 54.6,5.842 54.6,7.075 54.6,8.519 54.102,9.017 42.592,9.017 42.475,8.9 40.825,8.9 40.825,8.128 42.1,8.128 53.086,8.128 53.34,7.874 53.34,5.842
  pour cut-out: 7.998,61.383 cw(c3.5,61.5) 3.5,57 cw(c3.5,61.5) -0.997,61.672 cw(c3.818,61.672) 3.314,66.46 cw(c2.905,61.383)
  pour cut-out: 75.002,61.383 ccw(c79.5,61.5) 79.5,57 ccw(c79.5,61.5) 83.997,61.672 ccw(c79.182,61.672) 79.686,66.46 ccw(c80.095,61.383)
  pour cut-out: 75.002,3.617 cw(c79.5,3.5) 79.5,8 cw(c79.5,3.5) 83.997,3.328 cw(c79.182,3.328) 79.686,-1.46 cw(c80.095,3.617)
  pour cut-out: 75.033,60.019 ccw(c75.033,59.986) 75,59.986
  pour cut-out: 7.998,3.617 ccw(c3.5,3.5) 3.5,8 ccw(c3.5,3.5) -0.997,3.328 ccw(c3.818,3.328) 3.314,-1.46 ccw(c2.905,3.617)
Bottom Layer:
  pour cut-out: 5.611,45.811 -0.012,45.811 -0.012,39.636 7.239,39.637 19.525,39.636 19.45,22.05 7.25,22.05 7.25,21.5 7.25,20.955 7.239,20.32 7.874,20.955 19.685,20.955 20.32,21.59 20.32,40.005 19.685,40.64 7.885,40.64 7.239,41.286 7.239,44.183
  pour cut-out: 56.515,0 69.215,0 69.215,4.953 68.58,5.588 57.15,5.588 56.515,4.953
  pour cut-out: 7.251,22.05 0,22.05 0,15.875 5.635,15.875 7.251,17.491
  region net 5V: 60.303,1.8 60.982,1.8 61.275,2.093 61.275,12.275 60.875,12.675 60.875,17.875 60.525,18.225 60.025,18.225 59.65,17.85 59.65,12.675 59.65,10.95 60.05,10.55 60.05,2.053
  pour cut-out: 7.998,61.383 cw(c3.5,61.5) 3.5,57 cw(c3.5,61.5) -0.997,61.672 cw(c3.818,61.672) 3.314,66.46 cw(c2.905,61.383)
  pour cut-out: 75.002,61.383 ccw(c79.5,61.5) 79.5,57 ccw(c79.5,61.5) 83.997,61.672 ccw(c79.182,61.672) 79.686,66.46 ccw(c80.095,61.383)
  pour cut-out: 75.002,3.617 cw(c79.5,3.5) 79.5,8 cw(c79.5,3.5) 83.997,3.328 cw(c79.182,3.328) 79.686,-1.46 cw(c80.095,3.617)
  pour cut-out: 7.998,3.617 ccw(c3.5,3.5) 3.5,8 ccw(c3.5,3.5) -0.997,3.328 ccw(c3.818,3.328) 3.314,-1.46 ccw(c2.905,3.617)

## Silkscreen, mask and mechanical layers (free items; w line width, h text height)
Top Overlay:
  drawing of 1480 lines, arcs and shapes, not listed
  text "Expansion GPIO" at 27.305,63.5 h1
  text "RESET" at 65.022,62.441 h1
  text "SW" at 70.483,62.441 h1
  text "GPIO D" at 16.256,61.976 h0.5
  text "GPIO C" at 28.321,61.976 h0.5
  text "GPIO B" at 39.116,61.976 h0.5
  text "GPIO A" at 49.911,61.976 h0.5
  text "J8" at 41.275,55.88 h0.5
  text "J9" at 42.672,55.88 h0.5
  text "J10" at 43.942,55.88 h0.5
  text "J11" at 45.593,55.88 h0.5
  text "RS232" at 77.343,55.499 h0.8
  text "GPIO" at 2.286,54.737 h0.5
  text "No" at 41.402,54.61 h0.5
  text "SHORT" at 43.942,54.61 h0.4
  text "DATA" at 77.343,54.356 h0.8
  text "WIZ750SR-EVB V1.0" at 58.86,53.6 h0.8
  text "1-2" at 41.275,53.34 h0.4
  text "Digital I/O" at 43.053,53.34 h0.4
  text "A" at 1.1,53.275 h0.5
  text "SW6" at 2.45,53.2 h0.5
  text "D4" at 4.8,53.2 h0.5
  text "TTL & RS232" at 63.305,52.33 h0.8
  text "2-3" at 41.148,52.07 h0.4
  text "Analog In" at 43.18,52.07 h0.4
  text "SW7" at 2.45,51.725 h0.5
  text "D5" at 4.8,51.725 h0.5
  text "B" at 1.1,51.7 h0.5
  text "1" at 60.706,50.673 h0.5
  text "2" at 63.119,50.673 h0.5
  text "3" at 65.659,50.673 h0.5
  text "4" at 68.199,50.673 h0.5
  text "SW8" at 2.45,50.225 h0.5
  text "D6" at 4.8,50.175 h0.5
  text "C" at 1.075,50.15 h0.5
  text "J7" at 42.037,50.038 h0.5
  text "OPEN" at 45.212,48.768 h0.4
  text "SHORT" at 41.55,48.725 h0.4
  text "D" at 1.075,48.675 h0.5
  text "SW9" at 2.45,48.675 h0.5
  text "No" at 38.862,48.641 h0.5
  text "D7" at 4.7,48.575 h0.5
  text "1-2" at 38.862,47.371 h0.4
  text "NORMAL" at 41.3,47.375 h0.4
  text "ISP" at 45.466,47.371 h0.4
  text "J1" at 50.292,43.307 h0.5
  text "J2" at 51.689,43.307 h0.5
  text "J3" at 53.34,43.307 h0.5
  text "J4" at 54.864,43.307 h0.5
  text "No" at 50.038,41.783 h0.5
  text "1" at 52.07,41.783 h0.5
  text "2" at 53.213,41.783 h0.5
  text "3" at 54.483,41.783 h0.5
  text "4" at 55.753,41.783 h0.5
  text "J16" at 16.002,41.402 h0.76
  text "J15" at 22.606,41.402 h0.76
  text "J13" at 38.659,38.887 h0.76
  text "No" at 50.165,35.179 h0.5
  text "TTL" at 52.324,35.179 h0.4
  text "RS232" at 54.483,35.179 h0.4
  text "1-2" at 50.038,33.782 h0.4
  text "SHORT" at 51.943,33.782 h0.4
  text "2-3" at 50.038,32.385 h0.4
  text "SHORT" at 54.356,32.385 h0.4
  text "3-4" at 50.038,31.115 h0.4
  text "SHORT" at 51.943,31.115 h0.4
  text "POWER" at 54.483,19.812 h0.8
  text "J14" at 17.704,19.583 h0.76
  text "LED" at 54.483,18.669 h0.8
  text "SHORT" at 47.24,18.579 h0.4
  text "No" at 45.974,18.542 h0.4
  text "OPEN" at 50.546,18.542 h0.4
  text "J5" at 45.974,17.272 h0.4
  text "DTR" at 47.625,17.272 h0.4
  text "PHY_LINK" at 49.784,17.272 h0.4
  text "J6" at 45.974,16.002 h0.4
  text "DSR" at 47.625,16.002 h0.4
  text "HW_TRIG" at 49.911,16.002 h0.4
  text "APP_BOOT" at 3.759,13.792 h0.5
  text "Normal" at 8.636,13.792 h0.5
  text "BOOT" at 23.216,13.792 h0.5
  text "BOOT" at 23.2,11.125 h0.5
  text "BOOT" at 4.775,11.074 h0.5
  text "Normal" at 8.675,11.075 h0.5
  text "POWER" at 72.771,9.271 h0.8
  text "Normal" at 8.636,8.433 h0.5
  text "HW_TRIG" at 4.013,8.407 h0.5
  text "Command" at 22.479,8.382 h0.5
  text "5V" at 72.771,8.128 h0.8
  text "Slide" at 7.493,5.969 h0.8
  text "ISP Debug Port" at 19.975,4.85 h0.8
  text "SW" at 9.525,4.699 h0.8
  text "POWER" at 54.61,2.54 h0.6
  text "POWER" at 67.945,2.54 h0.6
  text "SW" at 54.6,1.75 h0.6
  text "SW" at 67.925,1.75 h0.6
  text "USB" at 42.418,1.651 h0.8
  text "ON" at 54.6,0.925 h0.6
  text "OFF" at 67.925,0.925 h0.6
  text "GND" at 29.775,0.825 h0.5
  text "VCC" at 17.15,0.8 h0.5
  text "BOOT" at 19.45,0.8 h0.5
  text "RXD" at 22.15,0.8 h0.5
  text "TXD" at 24.675,0.8 h0.5
  text "DEBUG" at 40.767,0.508 h0.8
Mechanical 2:
  text "BOARD NAME : WIZ750SR_EVB TTL/232" at 0.127,83.693 h1.52
  text "VERSION : V1.0" at 0.127,80.899 h1.52
  text "SIZE : 83mmX65mmX1.6T" at 0.127,78.105 h1.52
  text "LAYER : 2L  1.6T" at 0.127,75.438 h1.52
  text "GERBER DATE : 2016.05.24" at 0.127,72.644 h1.52
  text "Designed by WIZnet" at -0.127,68.58 h5.08

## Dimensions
0,3 to 83,3 on Keep-Out Layer
3,0 to 3,65 on Keep-Out Layer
